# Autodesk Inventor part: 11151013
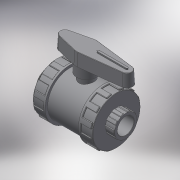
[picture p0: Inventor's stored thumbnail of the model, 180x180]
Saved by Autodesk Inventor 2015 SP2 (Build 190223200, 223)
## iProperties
Created: 2017-11
Part Number: 11151013
Material: Generic
Description: 2/NUT VALVE FEMALE THREAD 1 1/4" PVC
Document SubType Name: Modeling
Designer: KIM
Density: 1 g/cm^3
Appearance: Default
Author: KIM
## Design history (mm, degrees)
derived "111510.ipt"
feature "Solid1::111510.ipt"
tag "TaggingFeature1"
body "Solid1"
other parameters: "d1" = 38.952, "d3" = 22, "d4" = 31.1616, "d5" = 15.4, "d7" = 54.5328, "d8" = 72, "d13" = 1.16856, "d23" = 22, "d24" = 76.8, "d25" = 0.77904, "d26" = 1.16856, "d27" = 12, "d28" = 6, "d29" = 16.5, "d30" = 0, "d35" = 1.16856, "d45" = 360 deg, "d47" = 0.77904, "d50" = 44, "d51" = 24, "d53" = 0, "d55" = 7.7904, "d56" = 3.8952, "d57" = 15.4, "d58" = 0, "d59" = 1.16856, "d61" = 360 deg, "d63" = 32, "d64" = 74, "d66" = 96, "d68" = 16, "d69" = 28.8, "d70" = 18.5, "d71" = 3 deg, "d73" = 1.6, "d74" = 38.4, "d75" = 2.22, "d76" = 0, "d77" = 0.77904, "G_" = 38.952, "l_" = 22, "F_" = 74, "J_" = 96, "d67" = 32, "d72" = 8
